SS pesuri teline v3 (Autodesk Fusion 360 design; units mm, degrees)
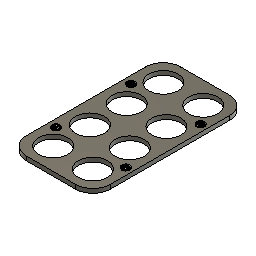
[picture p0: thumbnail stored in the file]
sketch "Sketch1" plane through (0, 0, 0) normal (0, 1, 0) x axis (1, 0, 0)
  line L1 (60, -110) -> (-60, -110)
  line L2 (60, 110) -> (60, -110)
  line L3 (-60, 110) -> (60, 110)
  line L4 (-60, -110) -> (-60, 110)
  line L5 (60, 110) -> (-60, -110)
  line L6 (-60, 110) -> (60, -110)
  point P6 (0, 0)
  point P1 (0, 0)
  point P4 (60, 110)
  point P5 (-60, 110)
  point P3 (60, -110)
  horizontal L1
  perpendicular L1 L2
  parallel L1 L3
  parallel L2 L4
  coincident L5 P6
  coincident L6 P6
  coincident P1 P6
  dimension "d1" distance P4 P5 = 120
  dimension "d2" distance P3 P4 = 220
extrude "Extrude1" new body sketch "Sketch1" profile of L1 L2 L3 L4 along normal blind 6
fillet "Fillet1" radius 25
sketch "Sketch2" plane through (0, 6, 0) normal (0, 1, 0) x axis (-1, 0, 0)
  line L1 (35, -110) -> (-35, -110)
  line L2 (60, 85) -> (60, -85)
  line L3 (-35, 110) -> (35, 110)
  line L4 (-60, -85) -> (-60, 85)
  arc A1 centre (-35, -85) radius 25 clockwise from (-35, -110) to (-60, -85)
  arc A2 centre (35, -85) radius 25 clockwise from (60, -85) to (35, -110)
  arc A3 centre (35, 85) radius 25 clockwise from (35, 110) to (60, 85)
  arc A4 centre (-35, 85) radius 25 clockwise from (-60, 85) to (-35, 110)
  circle C1 centre (28.0485, -78.6332) radius 20.75
  circle C2 centre (-28.6865, -78.6332) radius 20.75
  circle C3 centre (28.0485, -26.2112) radius 20.75
  circle C4 centre (-28.6865, -26.2112) radius 20.75
  circle C5 centre (28.0485, 26.2108) radius 20.75
  circle C6 centre (-28.6865, 26.2108) radius 20.75
  circle C7 centre (28.0485, 78.6328) radius 20.75
  circle C8 centre (-28.6865, 78.6328) radius 20.75
  dimension "d7" diameter C1 = 41.5
  dimension "d10" R-Pattern1-uDistance = -56.735
  dimension "d11" R-Pattern1-vDistance = 157.266
extrude "Extrude2" cut sketch "Sketch2" profile of C1 C2 C3 C4 C5 C6 C7 C8 against normal blind 10
sketch "Sketch3" plane through (0, 6, 0) normal (0, 1, 0) x axis (-1, 0, 0)
  line L1 (35, -110) -> (-35, -110)
  line L2 (60, 85) -> (60, -85)
  line L3 (-35, 110) -> (35, 110)
  line L4 (-60, -85) -> (-60, 85)
  circle C1 centre (-28.6865, 26.2108) radius 20.75
  circle C2 centre (28.0485, -26.2112) radius 20.75
  circle C3 centre (28.0485, 26.2108) radius 20.75
  circle C4 centre (-28.6865, -26.2112) radius 20.75
  circle C5 centre (-28.6865, 78.6328) radius 20.75
  circle C6 centre (28.0485, -78.6332) radius 20.75
  circle C7 centre (28.0485, 78.6328) radius 20.75
  circle C8 centre (-28.6865, -78.6332) radius 20.75
  arc A1 centre (-35, -85) radius 25 clockwise from (-35, -110) to (-60, -85)
  arc A2 centre (35, -85) radius 25 clockwise from (60, -85) to (35, -110)
  arc A3 centre (35, 85) radius 25 clockwise from (35, 110) to (60, 85)
  arc A4 centre (-35, 85) radius 25 clockwise from (-60, 85) to (-35, 110)
  circle C9 centre (49.7902, 53.4784) radius 6
  circle C10 centre (-49.6058, 53.4784) radius 6
  circle C11 centre (49.7902, -53.4786) radius 6
  circle C12 centre (-49.6058, -53.4786) radius 6
  dimension "d14" diameter C9 = 12
  dimension "d17" R-Pattern1-uDistance = -99.396
  dimension "d18" R-Pattern1-vDistance = -106.957
extrude "Extrude3" cut sketch "Sketch3" profile of C9 C10 C11 C12 against normal blind 10
thread "Thread1" ThreadOffset 0 ThreadLength 10
thread "Thread2" ThreadOffset 0 ThreadLength 10
thread "Thread3" ThreadOffset 0 ThreadLength 10
thread "Thread4" ThreadOffset 0 ThreadLength 10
